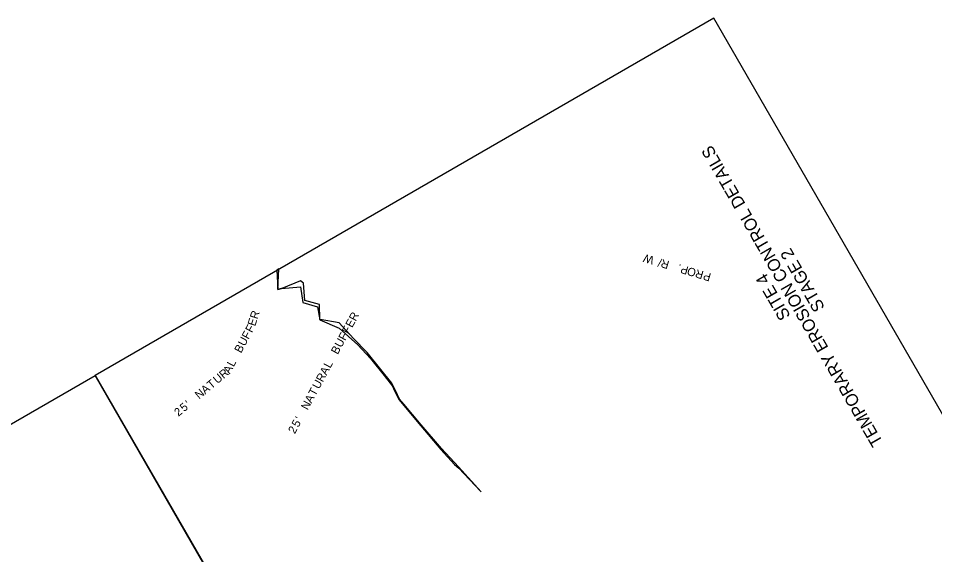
# Model space of a CAD drawing. Extents: x 956270 to 957915, y 1920230 to 1922423.
# Drawn here: x 956610 to 957279, y 1922032 to 1922423 of the extents above; entities that cross this region are included whole.
import ezdxf

# ---------------------------------------------------------------- set-up
doc = ezdxf.new("R2010")
doc.units = 0
for name, color, linetype in [('1', 7, 'Continuous'), ('60', 7, 'Continuous'), ('NO PLOT', 7, 'Continuous'), ('R_Draft', 7, 'Continuous')]:
    doc.layers.add(name, color=color, linetype=linetype)

msp = doc.modelspace()

# ---------------------------------------------------------------- linework, layer by layer
at = {"layer": '1'}
msp.add_line((956816.66, 1921901.98), (956666.17, 1922162.65), dxfattribs=at)
at = {"layer": 'NO PLOT'}
for points in [[(957915.18, 1921041.6), (957117.5, 1922423.23), (956666.17, 1922162.65), (956816.66, 1921901.98), (956875.12, 1921935.73), (957087.62, 1921567.67), (957029.16, 1921533.92), (957172.25, 1921286.08), (957225.74, 1921316.96), (957397.07, 1921020.21), (957343.58, 1920989.33), (957463.85, 1920781.02)], [(957915.18, 1921041.6), (957117.5, 1922423.23), (956666.17, 1922162.65), (956816.66, 1921901.98), (956875.12, 1921935.73), (957087.62, 1921567.67), (957029.16, 1921533.92), (957172.25, 1921286.08), (957225.74, 1921316.96), (957397.07, 1921020.21), (957343.58, 1920989.33), (957463.85, 1920781.02)], [(957915.18, 1921041.6), (957117.5, 1922423.23), (956666.17, 1922162.65), (956816.66, 1921901.98), (956875.12, 1921935.73), (957087.62, 1921567.67), (957029.16, 1921533.92), (957172.25, 1921286.08), (957225.74, 1921316.96), (957397.07, 1921020.21), (957343.58, 1920989.33), (957463.85, 1920781.02)], [(957915.18, 1921041.6), (957117.5, 1922423.23), (956666.17, 1922162.65), (956816.66, 1921901.98), (956875.12, 1921935.73), (957087.62, 1921567.67), (957029.16, 1921533.92), (957172.25, 1921286.08), (957225.74, 1921316.96), (957397.07, 1921020.21), (957343.58, 1920989.33), (957463.85, 1920781.02)], [(957915.18, 1921041.6), (957117.5, 1922423.23), (956666.17, 1922162.65), (956816.66, 1921901.98), (956875.12, 1921935.73), (957087.62, 1921567.67), (957029.16, 1921533.92), (957172.25, 1921286.08), (957225.74, 1921316.96), (957397.07, 1921020.21), (957343.58, 1920989.33), (957463.85, 1920781.02)], [(956931.44, 1922095.01), (956947.29, 1922078.32), (956947.79, 1922077.88), (956947.79, 1922077.88), (956931.31, 1922096.14), (956918.86, 1922109.38), (956904, 1922126.72), (956891.38, 1922141.69), (956888.23, 1922145.54), (956885.38, 1922151.69), (956882.65, 1922157), (956864.75, 1922179.49), (956854.58, 1922189.68), (956844.34, 1922201), (956830.44, 1922203.45), (956830.11, 1922203.5), (956830.08, 1922203.66), (956829.97, 1922214.45), (956819.09, 1922217.49), (956818.17, 1922230.06), (956815.92, 1922231.72), (956802.3, 1922226.15), (956802.15, 1922226.09), (956799.41, 1922225.37), (956800.24, 1922240.5), (956798.86, 1922239.41), (956799.41, 1922225.37), (956802.15, 1922226.08), (956815.92, 1922227.29), (956817.7, 1922216.02), (956828.35, 1922212.79), (956830.04, 1922203.36), (956844.2, 1922197.22), (956857.75, 1922185.16), (956867.17, 1922175.06), (956877.18, 1922162.78), (956883.13, 1922154.88), (956884.67, 1922151.51), (956885.93, 1922149.01), (956887.75, 1922145.08), (956891.31, 1922140.91), (956903.79, 1922125.87), (956918.34, 1922108.76), (956928.33, 1922097.77)], [(957012.51, 1920520.44), (956420.48, 1921545.87), (956463.26, 1921570.57), (956365.36, 1921740.14), (956378, 1921747.44), (956270.25, 1921934.07), (956666.17, 1922162.65), (956816.66, 1921901.98), (956749.98, 1921863.48), (956962.48, 1921495.42), (957029.16, 1921533.92), (957172.25, 1921286.08), (957120.9, 1921256.43), (957292.23, 1920959.68), (957343.58, 1920989.33), (957463.85, 1920781.02)], [(957012.51, 1920520.44), (956420.48, 1921545.87), (956463.26, 1921570.57), (956365.36, 1921740.14), (956378, 1921747.44), (956270.25, 1921934.07), (956666.17, 1922162.65), (956816.66, 1921901.98), (956749.98, 1921863.48), (956962.48, 1921495.42), (957029.16, 1921533.92), (957172.25, 1921286.08), (957120.9, 1921256.43), (957292.23, 1920959.68), (957343.58, 1920989.33), (957463.85, 1920781.02)], [(957012.51, 1920520.44), (956420.48, 1921545.87), (956463.26, 1921570.57), (956365.36, 1921740.14), (956378, 1921747.44), (956270.25, 1921934.07), (956666.17, 1922162.65), (956816.66, 1921901.98), (956749.98, 1921863.48), (956962.48, 1921495.42), (957029.16, 1921533.92), (957172.25, 1921286.08), (957120.9, 1921256.43), (957292.23, 1920959.68), (957343.58, 1920989.33), (957463.85, 1920781.02)], [(957012.51, 1920520.44), (956420.48, 1921545.87), (956463.26, 1921570.57), (956365.36, 1921740.14), (956378, 1921747.44), (956270.25, 1921934.07), (956666.17, 1922162.65), (956816.66, 1921901.98), (956749.98, 1921863.48), (956962.48, 1921495.42), (957029.16, 1921533.92), (957172.25, 1921286.08), (957120.9, 1921256.43), (957292.23, 1920959.68), (957343.58, 1920989.33), (957463.85, 1920781.02)], [(957012.51, 1920520.44), (956420.48, 1921545.87), (956463.26, 1921570.57), (956365.36, 1921740.14), (956378, 1921747.44), (956270.25, 1921934.07), (956666.17, 1922162.65), (956816.66, 1921901.98), (956749.98, 1921863.48), (956962.48, 1921495.42), (957029.16, 1921533.92), (957172.25, 1921286.08), (957120.9, 1921256.43), (957292.23, 1920959.68), (957343.58, 1920989.33), (957463.85, 1920781.02)]]:
    msp.add_lwpolyline(points, close=True, dxfattribs=at)

# ---------------------------------------------------------------- texts
at = {"layer": '60'}
for s, p in [('TEMPORARY EROSION CONTROL DETAILS', (957241.19, 1922114.13)), ('STAGE 2', (957198.79, 1922212.31)), ('SITE 4', (957173.78, 1922206.14))]:
    msp.add_text(s, height=9, rotation=120, dxfattribs=at).set_placement(p)
at = {"layer": 'R_Draft'}
for s, rotation, p in [('W', 163.52972, (957074.46, 1922249.25)), ('/', 163.52972, (957080.08, 1922247.58)), ('R', 163.52972, (957085.51, 1922245.98)), ('.', 163.52972, (957094.08, 1922243.45)), ('P', 163.52972, (957099.51, 1922241.84)), ('O', 163.52972, (957105.13, 1922240.18)), ('R', 163.52972, (957110.57, 1922238.57)), ('P', 163.52972, (957116, 1922236.96)), ('R', 71.87823, (956784.61, 1922203.37)), ('E', 71.87823, (956782.93, 1922198.25)), ('E', 61.63528, (956853.7, 1922197.11)), ('R', 61.63528, (956856.26, 1922201.85)), ('F', 61.63528, (956780.65, 1922193.39)), ('F', 61.63528, (956851.14, 1922192.37)), ('U', 61.63528, (956775.36, 1922183.58)), ('F', 61.63528, (956778.09, 1922188.65)), ('U', 61.63528, (956845.85, 1922182.56)), ('F', 61.63528, (956848.58, 1922187.64)), ('B', 61.63528, (956772.66, 1922178.59)), ('B', 61.63528, (956843.15, 1922177.58)), ('A', 61.63528, (956764.47, 1922163.41)), ('L', 61.63528, (956767.25, 1922168.57)), ('L', 61.63528, (956837.74, 1922167.56)), ('U', 39.9648, (956755.42, 1922156.31)), ('R', 39.9648, (956759.84, 1922160.01)), ('R', 61.63528, (956832.27, 1922157.41)), ('A', 61.63528, (956834.96, 1922162.4)), ('T', 39.9648, (956750.93, 1922152.54)), ('U', 61.63528, (956829.53, 1922152.34)), ('N', 39.9648, (956742.09, 1922145.14)), ('A', 39.9648, (956746.44, 1922148.78)), ('T', 61.63528, (956826.75, 1922147.19)), ('5', 39.9648, (956731.12, 1922135.94)), ("'", 39.9648, (956735.25, 1922139.4)), ('N', 61.63528, (956821.27, 1922137.04)), ('A', 61.63528, (956823.96, 1922142.03)), ('2', 39.9648, (956726.99, 1922132.49)), ('5', 61.63528, (956814.47, 1922124.45)), ("'", 61.63528, (956817.03, 1922129.19)), ('2', 61.63528, (956811.91, 1922119.71))]:
    msp.add_text(s, height=6, rotation=rotation, dxfattribs=at).set_placement(p)

doc.saveas('drawing.dxf')
